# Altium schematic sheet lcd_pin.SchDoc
size A
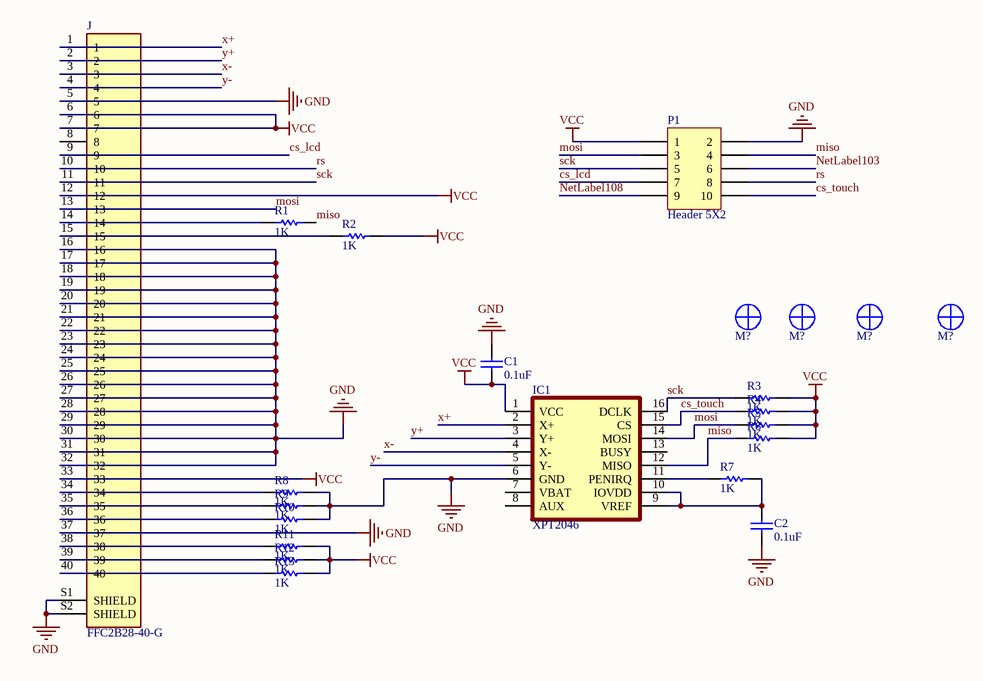
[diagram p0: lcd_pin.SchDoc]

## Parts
(Parts that share a designator on the sheet are numbered #1, #2 ... from top to bottom, then left to right.)
C1  0.1uF  [CAPC4817X12N]
C2  0.1uF  [CAPC4817X12N]
IC1  XPT2046  [TSSOP16]
J  FFC2B28-40-G  [GCT_FFC2B28-40-G]
M?#1  Screw  [Board Screw]  (value not drawn)
M?#2  Screw  [Board Screw]  (value not drawn)
M?#3  Screw  [Board Screw]  (value not drawn)
M?#4  Screw  [Board Screw]  (value not drawn)
P1  Header 5X2  [HDR2X5]
R1  1K  [RESC4817X04N]
R2  1K  [RESC4817X04N]
R3  1K  [RESC4817X04N]
R4  1K  [RESC4817X04N]
R5  1K  [RESC4817X04N]
R6  1K  [RESC4817X04N]
R7  1K  [RESC4817X04N]
R8  1K  [RESC4817X04N]
R9  1K  [RESC4817X04N]
R10  1K  [RESC4817X04N]
R11  1K  [RESC4817X04N]
R12  1K  [RESC4817X04N]
R13  1K  [RESC4817X04N]

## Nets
GND: C1.2 C2.1 IC1.6(GND) J.5 J.16 J.17 J.18 J.19 J.20 J.21 J.22 J.23 J.24 J.25 J.26 J.27 J.28 J.29 J.30 J.31 J.32 J.37 J.S1(SHIELD) J.S2(SHIELD) P1.2 R8.2 R9.2 R10.2
VCC: C1.1 IC1.1(VCC) J.6 J.7 J.12 J.33 P1.1 R2.2 R3.2 R4.2 R5.2 R6.2 R11.2 R12.2 R13.2
cs_lcd: J.9 P1.7
cs_touch: IC1.15(CS) P1.10 R4.1
miso: IC1.12(MISO) P1.4 R1.2 R6.1
mosi: IC1.14(MOSI) J.13 P1.3 R5.1
NetLabel103: P1.6
NetLabel108: P1.9
rs: J.10 P1.8
sck: IC1.16(DCLK) J.11 P1.5 R3.1
x+: IC1.2(X+) J.1
x-: IC1.4(X-) J.3
y+: IC1.3(Y+) J.2
y-: IC1.5(Y-) J.4
NetC2_2: C2.2 IC1.9(VREF) IC1.10(IOVDD) R7.2
NetIC1_11: IC1.11(PENIRQ) R7.1
NetJ_14: J.14 R1.1
NetJ_15: J.15 R2.1
NetJ_34: J.34 R8.1
NetJ_35: J.35 R9.1
NetJ_36: J.36 R10.1
NetJ_38: J.38 R11.1
NetJ_39: J.39 R12.1
NetJ_40: J.40 R13.1

Not connected (* = marked no-connect by the designer): IC1 7(VBAT) 8(AUX) 13(BUSY); J 8

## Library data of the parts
C1 C2 = CAP SMD 1206: CAP 1206; Designer: Abbas Basereh
IC1 = XPT2046: RASPBERRY PI 3.5 TFT DISPLAY; MF: Xptek
J = FFC2B28-40-G: 40 Position FFC, FPC Connector Contacts, Top and Bottom 0.020 _0.50mm_ Surface Mount, Right Angle; MF: Global Connector Technology
M?#1-M?#4 = Board Screw 3MM: Board Screw With Spacer
P1 = Header 5X2: Header, 5-Pin, Dual row
R1-R13 = RES 1206 0.25W: RES 1206; Designer: Abbas Basereh; Desc.: RES SMD 1206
